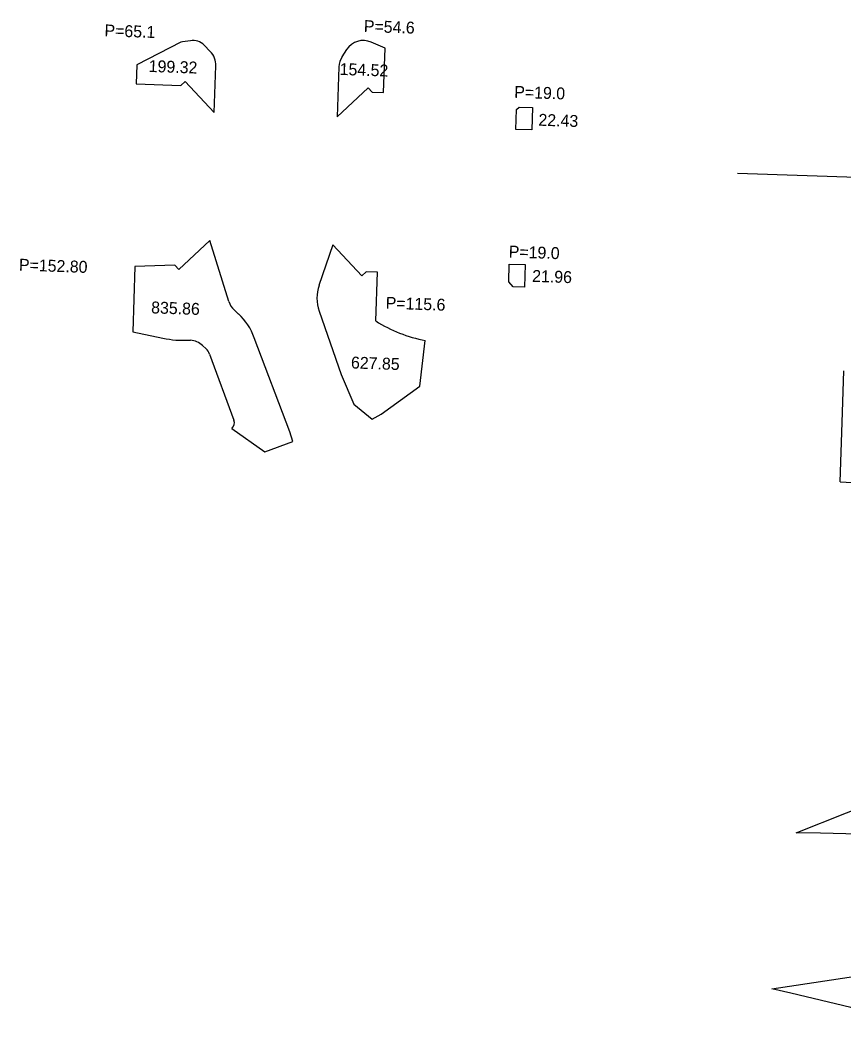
# Model space of a CAD drawing. Extents: x 2191309 to 2193046, y 863659 to 865133.
# Drawn here: x 2191308.8 to 2191516.5, y 864879 to 865132.6 of the extents above; entities that cross this region are included whole.
import ezdxf

# ---------------------------------------------------------------- set-up
doc = ezdxf.new("R2010")
doc.units = 0
for name, color, linetype in [('ANNOTATION', 7, 'Continuous'), ('D_Bridge_Abutment', 7, 'Continuous'), ('D_Roadway_Centerline', 7, 'Continuous'), ('D_Roadway_Edge_Shoulder', 7, 'Continuous'), ('D_Slope_Toe', 7, 'Continuous'), ('FRAME', 7, 'Continuous')]:
    doc.layers.add(name, color=color, linetype=linetype)

msp = doc.modelspace()

# ---------------------------------------------------------------- linework, layer by layer
at = {"layer": 'ANNOTATION'}
msp.add_line((2191498.38, 864888.35), (2191531.88, 864893.45), dxfattribs=at)
for points in [[(2191504.49, 864927.67), (2191529.85, 864937.74), (2191533.38, 864937.09), (2191555.19, 864947.2)], [(2191520.21, 864927.37), (2191510.58, 864927.56), (2191504.49, 864927.67)], [(2191616.74, 864879.19), (2191611.55, 864881.84), (2191609.63, 864882.92), (2191608.26, 864883.93), (2191603.05, 864883.77), (2191594.8, 864884), (2191578.03, 864883.86), (2191556.75, 864883.06), (2191556.26, 864883.09), (2191552.98, 864882.62), (2191527.84, 864879.01), (2191518.29, 864883.67), (2191503.11, 864887.23), (2191498.38, 864888.35)]]:
    msp.add_lwpolyline(points, dxfattribs=at)
at = {"layer": 'D_Bridge_Abutment'}
for p, q in [((2191351.69, 865127.39), (2191349.68, 865127.06)), ((2191356.72, 865124.67), (2191355.21, 865126.23)), ((2191391.1, 865125.14), (2191389.93, 865123.33)), ((2191400.81, 865125.48), (2191397.31, 865127.01)), ((2191400.43, 865114.32), (2191400.81, 865125.48)), ((2191357.73, 865109.25), (2191358.13, 865121.02)), ((2191389.14, 865120.79), (2191388.71, 865108.19)), ((2191349.3, 865116.08), (2191350.4, 865117.1)), ((2191350.4, 865117.1), (2191357.73, 865109.25)), ((2191388.71, 865108.19), (2191396.56, 865115.52)), ((2191396.56, 865115.52), (2191397.58, 865114.42)), ((2191397.58, 865114.42), (2191400.43, 865114.32))]:
    msp.add_line(p, q, dxfattribs=at)
msp.add_lwpolyline([(2191349.68, 865127.06), (2191349.29, 865126.99), (2191338.18, 865121.3), (2191338.01, 865116.47), (2191349.3, 865116.08)], dxfattribs=at)
for centre, radius, start, end in [((2191352.34, 865123.44), 4, 44.1436, 99.3716), ((2191395.3, 865122.43), 5, 66.3138, 147.2162), ((2191353.13, 865121.19), 5, 358.0343, 44.1436), ((2191394.14, 865120.62), 5, 147.2162, 178.0343)]:
    msp.add_arc(centre, radius, start, end, dxfattribs=at)
at = {"layer": 'D_Roadway_Centerline'}
msp.add_line((2191489.64, 865093.99), (2191792.64, 865083.59), dxfattribs=at)
at = {"layer": 'D_Roadway_Edge_Shoulder'}
for p, q in [((2191516.06, 865031.1), (2191516.51, 865044.14)), ((2191515.55, 865016.16), (2191516.06, 865031.1))]:
    msp.add_line(p, q, dxfattribs=at)
msp.add_lwpolyline([(2191515.55, 865016.16), (2191520.14, 865015.91), (2191530.39, 865013.75), (2191547.88, 865009.27), (2191558.56, 865006.76), (2191560.48, 865006.31)], dxfattribs=at)
at = {"layer": 'D_Slope_Toe'}
for p, q in [((2191361.4, 865061.66), (2191356.62, 865077.03)), ((2191387.6, 865075.96), (2191384.13, 865065.7)), ((2191394.93, 865068.11), (2191387.6, 865075.96)), ((2191396.03, 865069.13), (2191394.93, 865068.11)), ((2191363.85, 865058.48), (2191362.76, 865059.5)), ((2191337.16, 865054.01), (2191344.75, 865052.39)), ((2191351.39, 865051.89), (2191351.69, 865051.87)), ((2191354.78, 865050.53), (2191355.65, 865049.71)), ((2191356.55, 865048.36), (2191362.66, 865031.74)), ((2191392.88, 865035.79), (2191397.56, 865031.94)), ((2191362.16, 865029.59), (2191370.49, 865023.72)), ((2191370.49, 865023.72), (2191377.52, 865026.31))]:
    msp.add_line(p, q, dxfattribs=at)
for points in [[(2191433.96, 865110.03), (2191434.64, 865110.66), (2191437.99, 865110.56), (2191437.79, 865104.89), (2191433.79, 865105.03)], [(2191432.13, 865071.07), (2191436.12, 865070.93), (2191435.93, 865065.28), (2191433.09, 865065.37), (2191431.97, 865066.57)]]:
    msp.add_lwpolyline(points, close=True, dxfattribs=at)
for points in [[(2191356.62, 865077.03), (2191348.77, 865069.7), (2191347.75, 865070.79), (2191337.72, 865070.47), (2191337.16, 865054.01)], [(2191398.45, 865056.72), (2191398.87, 865069.04), (2191396.03, 865069.13)], [(2191384.17, 865059.21), (2191389.73, 865043.23), (2191392.88, 865035.79)], [(2191377.52, 865026.31), (2191376.76, 865028.75), (2191367.81, 865052.51)], [(2191397.56, 865031.94), (2191399.77, 865033.2), (2191409.54, 865040.26), (2191410.95, 865051.8)]]:
    msp.add_lwpolyline(points, dxfattribs=at)
for centre, radius, start, end in [((2191393.61, 865062.5), 10, 161.3325, 199.2107), ((2191366.17, 865063.15), 5, 197.2695, 226.9321), ((2191353.26, 865047.16), 15.5, 20.1952, 46.9321), ((2191417.27, 865086.23), 35, 237.4643, 259.5928), ((2191349.96, 865076.85), 25, 257.9862, 273.2734), ((2191351.36, 865046.88), 5, 46.9321, 86.205), ((2191353.26, 865047.16), 3.5, 20.1952, 46.9321), ((2191360.79, 865031.04), 2, 313.437, 20.1952)]:
    msp.add_arc(centre, radius, start, end, dxfattribs=at)

# ---------------------------------------------------------------- texts
at = {"layer": 'FRAME'}
for s, p in [('P=54.6', (2191395.4, 865129.59)), ('P=65.1', (2191329.99, 865128.5)), ('199.32', (2191341.15, 865119.51)), ('154.52', (2191389.3, 865118.76)), ('P=19.0', (2191433.33, 865113)), ('22.43', (2191439.43, 865105.96)), ('P=19.0', (2191431.95, 865072.74)), ('P=152.80', (2191308.42, 865069.43)), ('21.96', (2191437.85, 865066.6)), ('835.86', (2191341.76, 865058.66)), ('P=115.6', (2191400.91, 865059.82)), ('627.85', (2191392.16, 865044.77))]:
    msp.add_text(s, height=3, rotation=358.0343, dxfattribs=at).set_placement(p)

doc.saveas('drawing.dxf')
